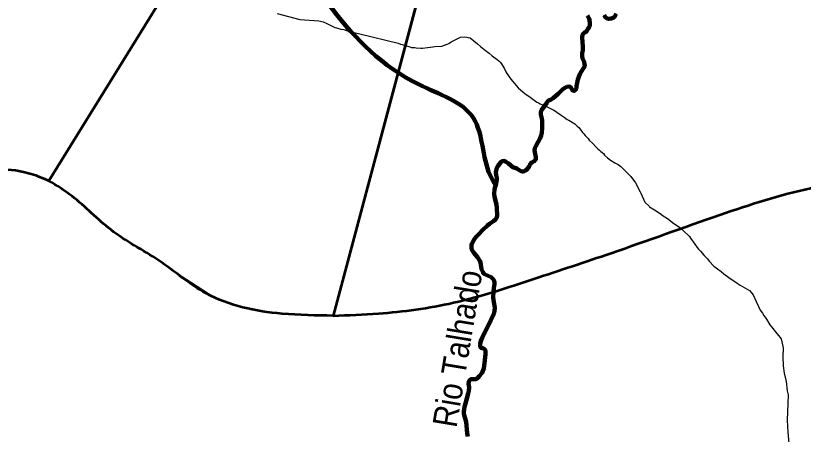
# Model space of a CAD drawing. Extents: x -1643653 to 4543381, y 1624270 to 13878484.
# Drawn here: x 611751 to 627893, y 8951494 to 8960077 of the extents above; entities that cross this region are included whole.
import ezdxf
from ezdxf.enums import TextEntityAlignment as Align

# ---------------------------------------------------------------- set-up
doc = ezdxf.new("R2010")
doc.units = 0
doc.header["$LTSCALE"] = 200
for name, color, linetype, lineweight in [('12', 7, 'Continuous', 25), ('24', 7, 'Continuous', 25), ('57', 7, 'Continuous', 13), ('59', 7, 'Continuous', 53), ('60', 7, 'Continuous', 13), ('9', 7, 'Continuous', 90)]:
    doc.layers.add(name, color=color, linetype=linetype, lineweight=lineweight)
doc.layers.add('49', color=7, linetype='Continuous')

msp = doc.modelspace()

# ---------------------------------------------------------------- linework, layer by layer
at = {"layer": '12'}
for points in [[(617107.9, 8960123.1), (617571.3, 8960000.1), (617961.2, 8959971.1), (617997, 8959967.1), (618026, 8959959.2), (618054, 8959949.2), (618114.7, 8959924.2), (618235.7, 8959862.3), (618293.7, 8959838.4), (618327.5, 8959827.4), (618413, 8959804.5), (618473.5, 8959791.6), (618533.2, 8959772.7), (618617.9, 8959748.8), (618652.5, 8959740.8), (618682.4, 8959731.8), (618711.4, 8959723.9), (618803.6, 8959709), (619586.3, 8959511.3)], [(619831.3, 8959436.2), (619865.1, 8959428.2), (619897.1, 8959423.3), (619929, 8959423.3), (619960.1, 8959421.4), (620056, 8959410.5), (620088, 8959410.6), (620193.3, 8959426.8), (620302, 8959438.9), (620338.3, 8959444), (620485.1, 8959452.2), (620592.3, 8959491.5), (620626.6, 8959508.6), (620677.1, 8959543.7), (620866.8, 8959636.1), (620950.1, 8959645.3), (621067.6, 8959622.4), (621213.8, 8959498.5), (621277.5, 8959446.5), (621310.7, 8959416.5), (621378.9, 8959364.5), (621451.2, 8959312.6), (621517.4, 8959257.6), (621620.6, 8959177.6), (621652, 8959151.6), (621681.1, 8959122.6), (621709.4, 8959090.6), (621730.8, 8959055.6), (621766, 8958989.6), (621797.6, 8958926.5), (621816.7, 8958894.5), (621897.9, 8958779.4), (622047.1, 8958598.4), (622104.4, 8958547.4), (622189, 8958482.4), (622295.2, 8958408.5), (622402.8, 8958323.5), (622432, 8958306.5), (622464.2, 8958290.6), (622503.3, 8958272.6), (622656.9, 8958198.7), (622695.9, 8958184.8), (622781.7, 8958137.8), (622814.5, 8958116.8), (622845, 8958100.9), (622933, 8958040.9), (622994, 8957997), (623055.6, 8957949), (623090.1, 8957935), (623208.6, 8957861.1), (623261.3, 8957811.1), (623293.1, 8957783.1), (623319, 8957753.1), (623370.1, 8957684.1), (623394.1, 8957657.1), (623423, 8957618), (623480.8, 8957556), (623503.5, 8957528), (623577.3, 8957455), (623634.3, 8957397), (623656.2, 8957377), (623681.5, 8957349), (623715.2, 8957318), (623746.4, 8957294), (623796.4, 8957250.1), (623820, 8957220), (623881.1, 8957162.1), (623907.7, 8957139.1), (623938.3, 8957116.1), (624032.6, 8957060.1), (624097.3, 8957025.2), (624126.4, 8957005.2), (624156.6, 8956982.2), (624209.6, 8956933.2), (624300.1, 8956843.2), (624356.6, 8956783.2), (624452.3, 8956653.2), (624547.5, 8956464), (624563.3, 8956437), (624643.8, 8956253.8), (624732.1, 8956169.8), (624741.4, 8956157.8), (624844.8, 8956096.9), (624963, 8956021), (625024.6, 8955976), (625106.9, 8955919.1), (625134.8, 8955896.1), (625215.8, 8955838.1), (625381.6, 8955722.2), (625453.3, 8955650.2), (625539.4, 8955570.2), (625559, 8955549.2), (625578.1, 8955517.2), (625672.3, 8955394.1), (625719.6, 8955321.1), (625744.1, 8955288.1), (625787.2, 8955246.1), (625865, 8955162.1), (625928.3, 8955090.1), (625962.8, 8955044), (626062.5, 8954941)], [(619586.3, 8959511.3), (619636.3, 8959496), (619674.1, 8959485), (619831.3, 8959436.2)], [(626062.5, 8954941), (626210.1, 8954830.1), (626263.6, 8954786.1), (626369.3, 8954710.2), (626395.7, 8954688.2), (626508.6, 8954610.2), (626539.2, 8954592.2), (626598.2, 8954554.3), (626792.1, 8954439.4), (626840.8, 8954390.4), (626864.8, 8954350.4), (626929.5, 8954214.3), (626976, 8954113.2), (627012.7, 8954042.1), (627056.3, 8953977.1), (627085.1, 8953931.1), (627140.4, 8953852), (627187.4, 8953773), (627209.8, 8953740), (627243.8, 8953694), (627268.1, 8953665), (627437.5, 8953449.9)], [(627437.5, 8953449.9), (627481.8, 8953267.7), (627474.2, 8953079.4), (627481, 8952894.1), (627502, 8952745.9), (627539.5, 8952577.7), (627565.1, 8952382.4), (627583.5, 8952301.3), (627578.9, 8952122), (627564.2, 8951783.5), (627578, 8951538.1), (627594.5, 8951309.8), (627615.6, 8951152.6), (627641.3, 8950944.3), (627690, 8950694), (627726.6, 8950540.8), (627780.8, 8950380.6), (627876.2, 8950172.5), (627886.3, 8950067.3), (627860.6, 8949911), (627825.7, 8949779.8), (627813.3, 8949686.6)]]:
    msp.add_lwpolyline(points, dxfattribs=at)
at = {"layer": '24'}
for points in [[(624056.4, 8960117.9), (624029.7, 8960062.8), (624008.5, 8960040.7), (623952.6, 8960017.6), (623906.6, 8960011.5), (623879.7, 8960018.5), (623839.9, 8960041.5), (623809.1, 8960087.5)], [(623469.3, 8960080), (623503, 8960016.9), (623511.8, 8959991.9), (623518.8, 8959918.8), (623515.2, 8959871.7), (623503, 8959841.6), (623483.8, 8959814.6), (623458.3, 8959764.4), (623435.3, 8959743.4), (623405.8, 8959733.3), (623380.1, 8959708.2), (623370, 8959684.2), (623363, 8959639.1), (623374, 8959437.8), (623371.3, 8959365.7), (623362.7, 8959309.6), (623359.5, 8959254.5), (623367, 8959203.4), (623399.7, 8959131.4), (623414.8, 8959045.2), (623404.2, 8959022.2), (623338.3, 8958926.9), (623315, 8958880.8), (623272.9, 8958769.6), (623243.1, 8958633.3), (623241.6, 8958590.3), (623234, 8958561.2), (623207.1, 8958537.1), (623180.9, 8958538.1), (623154, 8958559.1), (623142.4, 8958588.1), (623129.2, 8958606.1), (623114.3, 8958616.1), (623091.3, 8958624.1), (623048.1, 8958618)], [(623048.1, 8958618), (623008.6, 8958598.9), (622961, 8958563.8), (622867, 8958474.5), (622765.3, 8958385.2), (622710.3, 8958350.1), (622672.6, 8958336), (622645.8, 8958310.9), (622635.8, 8958292.8), (622526.4, 8958139.4), (622516.5, 8958114.4), (622511.7, 8958078.3), (622515.3, 8958048.3), (622533.3, 8957971.2), (622537.7, 8957930.1), (622539.2, 8957771.9), (622532.6, 8957678.7), (622519.6, 8957617.6), (622503, 8957566.5), (622414.7, 8957413.1), (622392.8, 8957358), (622387.2, 8957313.9), (622413.1, 8957173.7), (622412, 8957144.7), (622401.3, 8957121.6), (622379.3, 8957091.6), (622329.5, 8957067.4), (622303.6, 8957046.4), (622292.3, 8957028.3), (622277.2, 8956988.2), (622224.7, 8956922.1), (622199.4, 8956902), (622173.6, 8956888.9), (622144.5, 8956882.9), (622124.1, 8956884.8), (622082.2, 8956903.8), (622023.4, 8956940.8)], [(622023.4, 8956940.8), (621940, 8956970.7), (621852.9, 8957044.7), (621852.9, 8957044.7), (621788.3, 8957084.6), (621747.1, 8957098.6), (621722, 8957094.5), (621699.9, 8957079.5), (621630.5, 8956993.2), (621609.1, 8956955.1), (621593, 8956869), (621597.7, 8956809.9), (621609.5, 8956752.8), (621610.3, 8956716.8), (621596.7, 8956635.6), (621564.2, 8956517.4), (621555.7, 8956425.2), (621563.4, 8956363.1), (621602.1, 8956205), (621612.3, 8956132.8), (621617.2, 8955989.6), (621609.4, 8955942.6), (621581.9, 8955900.4), (621546.5, 8955864.3), (621462.3, 8955810.1), (621421.6, 8955778), (621315.5, 8955681.7), (621248.5, 8955606.5), (621180.3, 8955539.2), (621144.2, 8955490.1), (621090.8, 8955387.9), (621089.6, 8955318.8), (621102.6, 8955276.7), (621141.2, 8955216.7), (621216.2, 8955123.7), (621263.9, 8955050.6), (621273.7, 8955018.6), (621298.4, 8954880.4), (621326.6, 8954818.3), (621344.8, 8954792.3), (621361.2, 8954778.3), (621494.9, 8954716.5), (621540.7, 8954668.5), (621556.5, 8954637.4), (621563.9, 8954607.4), (621564.5, 8954574.3), (621548.8, 8954491.2), (621540.9, 8954424.1), (621539.7, 8954301.9), (621548, 8954202.7), (621568.6, 8954096.6), (621562.7, 8954019.5), (621547, 8953964.4), (621433.8, 8953717.8), (621371.7, 8953602.5), (621309.6, 8953474.2), (621290.3, 8953424.1), (621271.3, 8953352), (621268.5, 8953307.9), (621278.3, 8953276.9), (621286.8, 8953268.9), (621318.5, 8953261.9), (621350.1, 8953247.9), (621369.2, 8953222.9), (621379.6, 8953197.9)], [(621379.6, 8953197.9), (621378.8, 8953137.8), (621359.7, 8952949.5), (621342.4, 8952846.3), (621307.8, 8952755.1), (621249.5, 8952681.9), (621219.1, 8952650.8), (621195, 8952631.7), (621171.1, 8952622.7), (621146.2, 8952620.6), (621100.1, 8952625.6), (621079.8, 8952621.5), (621057, 8952606.5), (621039.6, 8952581.4), (621035.3, 8952565.4), (621033.6, 8952527.3), (621045.1, 8952461.2), (621037.1, 8952383.1), (621025.7, 8952328), (620968.5, 8952127.6), (620952.3, 8952055.4), (620937.5, 8951961.3), (620936.1, 8951922.2), (620941.1, 8951883.2), (620980.3, 8951750), (621003, 8951516.7), (621017.4, 8951444.6)]]:
    msp.add_lwpolyline(points, dxfattribs=at)
at = {"layer": '57'}
msp.add_line((618257.6, 8953925.9), (618207.3, 8953925.8), dxfattribs=at)
for points in [[(612430.2, 8956693.8), (612747.6, 8956491.3), (613132.8, 8956184), (613551.6, 8955800.6), (614057.6, 8955452.3), (614550.7, 8955141.9), (615023.2, 8954818.1), (615915.6, 8954244.4), (616589.2, 8954040), (617511.2, 8953947.5), (618207.3, 8953925.8), (618257.6, 8953925.9)], [(618207.3, 8953925.8), (617511.2, 8953947.5), (616589.2, 8954040), (615915.6, 8954244.4), (615023.2, 8954818.1), (614550.7, 8955141.9), (614057.6, 8955452.3), (613551.6, 8955800.6), (613132.8, 8956184), (612747.6, 8956491.3), (612430.2, 8956693.8)]]:
    msp.add_lwpolyline(points, dxfattribs=at)
for points in [[(606946.8, 8954087), (607164, 8954388.6), (607396.1, 8954883.6), (607870.9, 8955517.4), (608625.2, 8956035.7), (609416.9, 8956401.3), (612068.3, 8956835.4), (612430.2, 8956693.8)], [(612430.2, 8956693.8), (612068.3, 8956835.4), (609416.9, 8956401.3), (608625.2, 8956035.7), (607870.9, 8955517.4), (607396.1, 8954883.6), (607164, 8954388.6), (606946.8, 8954087)], [(618257.6, 8953925.9), (619183.7, 8953970.3), (620725.9, 8954192.9), (622371.6, 8954682.1), (623953.8, 8955209.7), (626185.5, 8955995.2), (628043.5, 8956541.4), (631351.2, 8956802.4), (633709.5, 8956728.8), (635993.8, 8956280.5), (637686.3, 8955648.2), (639291.4, 8954828.8), (640588.9, 8953973.3), (641709, 8952948.6), (643376.9, 8951340.4), (644721.9, 8950215.5), (645793.1, 8949290.9)], [(645793.1, 8949290.9), (644721.9, 8950215.5), (643376.9, 8951340.4), (641709, 8952948.6), (640588.9, 8953973.3), (639291.4, 8954828.8), (637686.3, 8955648.2), (635993.8, 8956280.5), (633709.5, 8956728.8), (631351.2, 8956802.4), (628043.5, 8956541.4), (626185.5, 8955995.2), (623953.8, 8955209.7), (622371.6, 8954682.1), (620725.9, 8954192.9), (619183.7, 8953970.3), (618257.6, 8953925.9)]]:
    msp.add_spline(points, degree=3, dxfattribs=at)
at = {"layer": '59'}
msp.add_line((621434.1, 8965861.3), (618257.6, 8953925.9), dxfattribs=at)
for points in [[(620631.9, 8965673.6), (621434.1, 8965861.3), (618257.6, 8953925.9), (618257.6, 8953925.9)], [(612430.1, 8956693.8), (617911.2, 8965554.7), (618251.3, 8965287.2), (618322.3, 8965231.4)], [(612430.2, 8956693.8), (617911.2, 8965554.7), (618251.3, 8965287.2), (618322.3, 8965231.4)]]:
    msp.add_lwpolyline(points, dxfattribs=at)
for points in [[(606956.6, 8954077.8), (607164, 8954388.6), (607396.1, 8954883.6), (607870.9, 8955517.4), (608625.2, 8956035.7), (609416.9, 8956401.3), (612068.3, 8956835.4), (612430.2, 8956693.8)], [(618257.6, 8953925.9), (619183.7, 8953970.3), (620725.9, 8954192.9), (622371.6, 8954682.1), (623953.8, 8955209.7), (626185.5, 8955995.2), (628043.5, 8956541.4), (631351.2, 8956802.4), (633709.5, 8956728.8), (635993.8, 8956280.5), (637686.3, 8955648.2), (639291.4, 8954828.8), (640588.9, 8953973.3), (641709, 8952948.6), (643376.9, 8951340.4), (644721.9, 8950215.5), (645793.1, 8949290.9)], [(618257.6, 8953925.9), (617209.7, 8953965.7), (615658.4, 8954379), (614681.6, 8955057.1), (613704.6, 8955684.2), (612906.2, 8956374.2), (612430.2, 8956693.8)]]:
    msp.add_spline(points, degree=3, dxfattribs=at)
at = {"layer": '60', "lineweight": 25}
msp.add_spline([(814781, 9009175.5), (814787.2, 9009173.4), (814796.9, 9009173.4), (814799.4, 9009172.4), (814805.1, 9009174.5), (814805.6, 9009176.5), (814811.7, 9009179.5), (814811.7, 9009179.5), (814801.5, 9009181), (814790.7, 9009181.5), (814784.1, 9009183.1), (814777.4, 9009185.1), (814778.4, 9009175.5)], degree=3, dxfattribs=at)
at = {"layer": '9'}
for points in [[(624056.4, 8960117.9), (624029.7, 8960062.8), (624008.5, 8960040.7), (623952.6, 8960017.6), (623906.6, 8960011.5), (623879.7, 8960018.5), (623839.9, 8960041.5), (623809.1, 8960087.5)], [(623469.3, 8960080), (623503, 8960016.9), (623511.8, 8959991.9), (623518.8, 8959918.8), (623515.2, 8959871.7), (623503, 8959841.6), (623483.8, 8959814.6), (623458.3, 8959764.4), (623435.3, 8959743.4), (623405.8, 8959733.3), (623380.1, 8959708.2), (623370, 8959684.2), (623363, 8959639.1), (623374, 8959437.8), (623371.3, 8959365.7), (623362.7, 8959309.6), (623359.5, 8959254.5), (623367, 8959203.4), (623399.7, 8959131.4), (623414.8, 8959045.2), (623404.2, 8959022.2), (623338.3, 8958926.9), (623315, 8958880.8), (623272.9, 8958769.6), (623243.1, 8958633.3), (623241.6, 8958590.3), (623234, 8958561.2), (623207.1, 8958537.1), (623180.9, 8958538.1), (623154, 8958559.1), (623142.4, 8958588.1), (623129.2, 8958606.1), (623114.3, 8958616.1), (623091.3, 8958624.1), (623048.1, 8958618)], [(623048.1, 8958618), (623008.6, 8958598.9), (622961, 8958563.8), (622867, 8958474.5), (622765.3, 8958385.2), (622710.3, 8958350.1), (622672.6, 8958336), (622645.8, 8958310.9), (622635.8, 8958292.8), (622526.4, 8958139.4), (622516.5, 8958114.4), (622511.7, 8958078.3), (622515.3, 8958048.3), (622533.3, 8957971.2), (622537.7, 8957930.1), (622539.2, 8957771.9), (622532.6, 8957678.7), (622519.6, 8957617.6), (622503, 8957566.5), (622414.7, 8957413.1), (622392.8, 8957358), (622387.2, 8957313.9), (622413.1, 8957173.7), (622412, 8957144.7), (622401.3, 8957121.6), (622379.3, 8957091.6), (622329.5, 8957067.4), (622303.6, 8957046.4), (622292.3, 8957028.3), (622277.2, 8956988.2), (622224.7, 8956922.1), (622199.4, 8956902), (622173.6, 8956888.9), (622144.5, 8956882.9), (622124.1, 8956884.8), (622082.2, 8956903.8), (622023.4, 8956940.8)], [(622023.4, 8956940.8), (621940, 8956970.7), (621852.9, 8957044.7), (621852.9, 8957044.7), (621788.3, 8957084.6), (621747.1, 8957098.6), (621722, 8957094.5), (621699.9, 8957079.5), (621630.5, 8956993.2), (621609.1, 8956955.1), (621593, 8956869), (621597.7, 8956809.9), (621609.5, 8956752.8), (621610.3, 8956716.8), (621596.7, 8956635.6), (621564.2, 8956517.4), (621555.7, 8956425.2), (621563.4, 8956363.1), (621602.1, 8956205), (621612.3, 8956132.8), (621617.2, 8955989.6), (621609.4, 8955942.6), (621581.9, 8955900.4), (621546.5, 8955864.3), (621462.3, 8955810.1), (621421.6, 8955778), (621315.5, 8955681.7), (621248.5, 8955606.5), (621180.3, 8955539.2), (621144.2, 8955490.1), (621090.8, 8955387.9), (621089.6, 8955318.8), (621102.6, 8955276.7), (621141.2, 8955216.7), (621216.2, 8955123.7), (621263.9, 8955050.6), (621273.7, 8955018.6), (621298.4, 8954880.4), (621326.6, 8954818.3), (621344.8, 8954792.3), (621361.2, 8954778.3), (621494.9, 8954716.5), (621540.7, 8954668.5), (621556.5, 8954637.4), (621563.9, 8954607.4), (621564.5, 8954574.3), (621548.8, 8954491.2), (621540.9, 8954424.1), (621539.7, 8954301.9), (621548, 8954202.7), (621568.6, 8954096.6), (621562.7, 8954019.5), (621547, 8953964.4), (621433.8, 8953717.8), (621371.7, 8953602.5), (621309.6, 8953474.2), (621290.3, 8953424.1), (621271.3, 8953352), (621268.5, 8953307.9), (621278.3, 8953276.9), (621286.8, 8953268.9), (621318.5, 8953261.9), (621350.1, 8953247.9), (621369.2, 8953222.9), (621379.6, 8953197.9)], [(621379.6, 8953197.9), (621378.8, 8953137.8), (621359.7, 8952949.5), (621342.4, 8952846.3), (621307.8, 8952755.1), (621249.5, 8952681.9), (621219.1, 8952650.8), (621195, 8952631.7), (621171.1, 8952622.7), (621146.2, 8952620.6), (621100.1, 8952625.6), (621079.8, 8952621.5), (621057, 8952606.5), (621039.6, 8952581.4), (621035.3, 8952565.4), (621033.6, 8952527.3), (621045.1, 8952461.2), (621037.1, 8952383.1), (621025.7, 8952328), (620968.5, 8952127.6), (620952.3, 8952055.4), (620937.5, 8951961.3), (620936.1, 8951922.2), (620941.1, 8951883.2), (620980.3, 8951750), (621003, 8951516.7), (621017.4, 8951444.6)]]:
    msp.add_lwpolyline(points, dxfattribs=at)
msp.add_spline([(592698.5, 8977198.4), (599903.5, 8973292.7), (608459.2, 8968138.2), (612674.8, 8965332.6), (616842, 8962096.4), (620005, 8958671.2), (621134, 8957974.7), (621473.4, 8956805.3), (621586.2, 8956597.5)], degree=3, dxfattribs=at)

# ---------------------------------------------------------------- texts
at = {"layer": '49', "width": 0.9}
msp.add_text('Rio Talhado', height=500, rotation=80.538, dxfattribs=at).set_placement((621050.4, 8953212.3), align=Align.CENTER)

doc.saveas('drawing.dxf')
